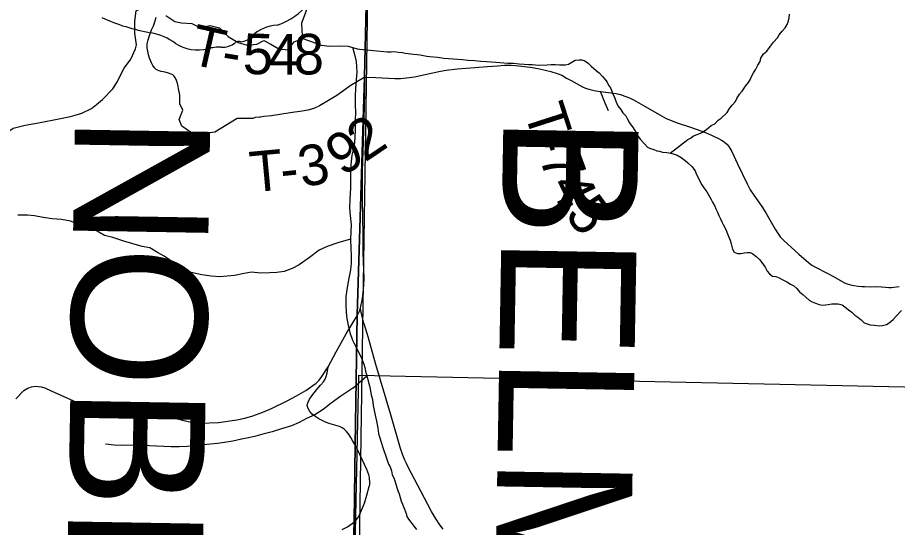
# Model space of a CAD drawing. Extents: x 0 to 34, y 0 to 22.
# Drawn here: x 26.601 to 27.832, y 19.383 to 20.097 of the extents above; entities that cross this region are included whole.
import ezdxf

# ---------------------------------------------------------------- set-up
doc = ezdxf.new("R2010")
doc.units = 0
for name, color, linetype in [('GM_X_Corporation', 7, 'Continuous'), ('GM_X_County', 7, 'Continuous'), ('GM_X_County_Text', 7, 'Continuous'), ('GM_X_Minor_River', 7, 'Continuous'), ('GM_X_State_Route', 7, 'Continuous'), ('GM_X_State_Shield', 7, 'Continuous'), ('GM_X_Township_Road', 7, 'Continuous'), ('GM_X_Township_Road_Text', 7, 'Continuous')]:
    doc.layers.add(name, color=color, linetype=linetype)

msp = doc.modelspace()

# ---------------------------------------------------------------- linework, layer by layer
at = {"layer": 'GM_X_Corporation'}
for points in [[(30.3167, 20.9), (27.1022, 20.9), (27.0898, 20.417), (27.0897, 20.4135), (27.089, 20.3692), (27.0873, 20.2665), (27.0907, 20.123), (27.0885, 20.1139), (27.0864, 20.0138), (27.0761, 19.6806), (27.0733, 19.498), (27.0719, 19.3912), (27.0487, 18.5805), (27.0419, 17.8236), (27.0349, 17.5522), (27.0234, 16.6611), (27.0124, 14.988), (27.0057, 14.5136), (27.2999, 14.5107), (27.8031, 14.5091), (28.4032, 14.497)], [(29.5503, 20.3788), (27.6751, 20.4106), (27.5829, 20.4116), (27.2336, 20.4152), (27.1239, 20.4163), (27.0898, 20.417), (27.0897, 20.4135), (27.089, 20.3692), (27.0873, 20.2665), (27.0907, 20.123), (27.0885, 20.1139), (27.0864, 20.0138), (27.0761, 19.6806), (27.0733, 19.498), (27.0719, 19.3912), (27.0487, 18.5805), (27.0419, 17.8236), (27.0349, 17.5522), (27.0234, 16.6611), (27.0124, 14.988), (27.0057, 14.5136), (27.2999, 14.5107), (27.8031, 14.5091), (28.4032, 14.497)], [(27.0234, 16.6611), (27.0349, 17.5522), (27.0419, 17.8236), (27.0487, 18.5805), (27.0719, 19.3912), (27.0733, 19.498), (27.0761, 19.6806), (27.0864, 20.0138), (27.0885, 20.1139), (27.0907, 20.123), (27.0873, 20.2665), (27.0031, 20.2673), (26.7822, 20.2704), (26.7196, 20.2707), (26.6351, 20.2734), (26.5702, 20.276), (26.2533, 20.2773), (25.4507, 20.2949), (24.5249, 20.3107), (24.0688, 20.3165), (24.0328, 20.3169), (23.5167, 20.3276), (23.5167, 14.5642)], [(27.0234, 16.6611), (27.0349, 17.5522), (27.0419, 17.8236), (27.0487, 18.5805), (27.0719, 19.3912), (27.0733, 19.498), (27.0761, 19.6806), (27.0864, 20.0138), (27.0885, 20.1139), (27.0907, 20.123), (27.0873, 20.2665), (27.0031, 20.2673), (26.7822, 20.2704), (26.7196, 20.2707), (26.6351, 20.2734), (26.5702, 20.276), (26.2533, 20.2773), (25.4507, 20.2949), (24.5249, 20.3107), (24.0688, 20.3165), (24.0328, 20.3169), (23.5167, 20.3276), (23.5167, 14.5642)]]:
    msp.add_lwpolyline(points, dxfattribs=at)
msp.add_lwpolyline([(27.9077, 19.5783), (27.8861, 18.5601), (27.0567, 18.5863), (27.0782, 19.5962)], close=True, dxfattribs=at)
at = {"layer": 'GM_X_County'}
msp.add_line((27.1022, 20.9), (27.0057, 14.5136), dxfattribs=at)
at = {"layer": 'GM_X_Minor_River'}
for points in [[(27.0002, 20.0673), (26.999, 20.0773), (26.9985, 20.0894), (27.0036, 20.1032), (27.0073, 20.1142), (27.0139, 20.1264), (27.0199, 20.1364), (27.0327, 20.1407), (27.0459, 20.1439), (27.0602, 20.1464), (27.0715, 20.1548), (27.0717, 20.1674), (27.0761, 20.1769), (27.0825, 20.1846)], [(26.8081, 20.0999), (26.8207, 20.0914), (26.8302, 20.0896), (26.8446, 20.0886), (26.8556, 20.0831), (26.87, 20.0856), (26.8832, 20.0823), (26.8955, 20.0703), (26.9096, 20.0618), (26.9221, 20.0581), (26.9353, 20.0598), (26.9455, 20.0649), (26.955, 20.0597), (26.9661, 20.053), (26.9793, 20.0516), (26.9879, 20.0628), (26.9999, 20.0675), (27.0132, 20.0627), (27.0258, 20.0583), (27.0379, 20.0566), (27.0515, 20.0571), (27.0636, 20.0569), (27.0761, 20.0532), (27.0798, 20.0525)], [(27.5144, 19.9071), (27.5388, 19.9259), (27.5426, 19.9279), (27.5471, 19.9314), (27.5535, 19.9338), (27.5587, 19.9361), (27.5651, 19.94), (27.5714, 19.9455), (27.5767, 19.9482), (27.5815, 19.9532), (27.5856, 19.9559), (27.5938, 19.9637), (27.5975, 19.9694), (27.6008, 19.974), (27.6056, 19.9794), (27.6075, 19.9836), (27.6115, 19.9898), (27.6149, 19.9936), (27.6196, 20.0009), (27.6237, 20.0059), (27.6267, 20.0105), (27.6281, 20.0144), (27.631, 20.0197), (27.6336, 20.0236), (27.6369, 20.0304), (27.6402, 20.0354), (27.6413, 20.04), (27.645, 20.0461), (27.6494, 20.05), (27.6546, 20.0569), (27.6587, 20.0623), (27.6646, 20.0685), (27.6668, 20.0727), (27.6709, 20.0777), (27.6753, 20.0827), (27.6779, 20.0873), (27.6797, 20.0923), (27.6808, 20.0965), (27.6814, 20.1014)], [(27.0693, 20.0552), (27.0717, 20.0471), (27.0748, 20.0354), (27.0754, 20.0206), (27.0744, 20.0103), (27.0738, 19.9974), (27.0732, 19.9868), (27.073, 19.9747), (27.0735, 19.9641), (27.0732, 19.9538), (27.073, 19.9394), (27.0728, 19.9288), (27.0718, 19.9174), (27.0686, 19.9044), (27.0672, 19.8908), (27.0666, 19.8813), (27.0667, 19.871), (27.0665, 19.8585), (27.0656, 19.8425), (27.0653, 19.8304), (27.0662, 19.8198), (27.0675, 19.8065), (27.0669, 19.7967), (27.0666, 19.7868), (27.0672, 19.7731), (27.0677, 19.7636), (27.0678, 19.753), (27.0668, 19.7435), (27.0643, 19.7317), (27.0626, 19.7215), (27.0601, 19.7063), (27.0603, 19.6926), (27.0612, 19.6782), (27.0633, 19.6657), (27.0657, 19.6559), (27.0696, 19.6453), (27.0714, 19.6415)], [(27.0798, 20.0525), (27.1182, 20.0487), (27.1238, 20.0488), (27.1276, 20.0492), (27.1341, 20.0486), (27.1394, 20.0479), (27.1432, 20.0472), (27.1473, 20.0465), (27.1549, 20.0455), (27.1598, 20.0452), (27.164, 20.0445), (27.1735, 20.0428), (27.1777, 20.0425), (27.1883, 20.0412), (27.1974, 20.0398), (27.2235, 20.038), (27.2315, 20.0374), (27.2402, 20.0368), (27.2493, 20.0358), (27.2569, 20.0352), (27.2702, 20.0343), (27.2868, 20.033), (27.2948, 20.0328), (27.3027, 20.0322), (27.3096, 20.0315), (27.3164, 20.0313), (27.3209, 20.031), (27.3255, 20.0307), (27.3293, 20.0304), (27.3421, 20.0306), (27.3478, 20.0311), (27.3538, 20.0312), (27.3595, 20.0309), (27.3641, 20.0306), (27.3679, 20.0307), (27.372, 20.0315), (27.3765, 20.0342), (27.3814, 20.037), (27.3866, 20.0378), (27.3904, 20.0375), (27.3946, 20.0361), (27.3992, 20.0331), (27.4035, 20.029), (27.4104, 20.0227), (27.4146, 20.0193), (27.4196, 20.0145), (27.4227, 20.0104), (27.4258, 20.0066), (27.4281, 20.0021), (27.4309, 19.9984), (27.4325, 19.9939), (27.434, 19.9901), (27.4368, 19.9841), (27.438, 19.9799), (27.4411, 19.9731), (27.445, 19.9679), (27.4481, 19.9634), (27.452, 19.9593), (27.4539, 19.9555), (27.4575, 19.9495), (27.4625, 19.9424), (27.466, 19.9364), (27.4687, 19.9315), (27.4722, 19.9266), (27.478, 19.9203), (27.4827, 19.9154), (27.4865, 19.9136), (27.4914, 19.9122), (27.4956, 19.9104), (27.4994, 19.9097), (27.5036, 19.9086), (27.5097, 19.9079), (27.5153, 19.9069), (27.5199, 19.9058), (27.5241, 19.904), (27.5298, 19.9007), (27.5352, 19.8966), (27.539, 19.8933), (27.5444, 19.8881), (27.5491, 19.8821), (27.5507, 19.8779), (27.5542, 19.8712), (27.5562, 19.867), (27.5585, 19.8625), (27.5612, 19.8584), (27.5655, 19.8528), (27.5694, 19.8464), (27.5714, 19.8422), (27.5737, 19.8385), (27.5768, 19.8329), (27.578, 19.8291), (27.5804, 19.8242), (27.5823, 19.8197), (27.5847, 19.8152), (27.5867, 19.811), (27.5882, 19.8073), (27.5922, 19.8001), (27.5945, 19.7941), (27.5965, 19.7892), (27.5981, 19.785), (27.5997, 19.7798)], [(27.0667, 19.7864), (27.0489, 19.7816), (27.0342, 19.7761), (27.023, 19.7711), (27.0091, 19.761), (26.9949, 19.7506), (26.9851, 19.7455), (26.9738, 19.7412), (26.9636, 19.74), (26.9538, 19.7394), (26.9409, 19.7389), (26.928, 19.7403), (26.9178, 19.7386), (26.9043, 19.7358), (26.8941, 19.7349), (26.8831, 19.734), (26.8718, 19.7346), (26.8585, 19.7367), (26.8437, 19.74), (26.8334, 19.7448), (26.8205, 19.7526), (26.806, 19.7626), (26.7964, 19.7678), (26.7858, 19.7745), (26.7748, 19.7763), (26.7603, 19.7807), (26.7493, 19.7836), (26.7338, 19.7887), (26.7224, 19.7919), (26.7121, 19.7979), (26.6999, 19.8027), (26.6897, 19.8063), (26.6748, 19.8118), (26.662, 19.814), (26.6491, 19.8149), (26.6362, 19.8167), (26.6244, 19.8192), (26.6146, 19.8202), (26.601, 19.82)], [(27.5997, 19.7798), (27.6017, 19.7726), (27.6037, 19.7684), (27.6083, 19.7666), (27.6132, 19.7667), (27.6177, 19.7672), (27.6219, 19.768), (27.626, 19.7677), (27.6298, 19.7659), (27.6345, 19.7622), (27.6391, 19.7581), (27.6425, 19.754), (27.6472, 19.7472), (27.65, 19.7416), (27.6534, 19.7378), (27.6576, 19.7345), (27.6622, 19.7342), (27.6668, 19.7324), (27.6721, 19.7298), (27.6775, 19.7269), (27.6828, 19.7235), (27.6874, 19.721), (27.6916, 19.7176), (27.6955, 19.7128), (27.7001, 19.709), (27.7089, 19.7012), (27.7128, 19.699), (27.7177, 19.6968), (27.7227, 19.695), (27.7268, 19.6943), (27.7318, 19.6944), (27.7355, 19.6952), (27.7404, 19.6961), (27.7446, 19.6962), (27.7495, 19.6959), (27.7548, 19.6945), (27.7587, 19.6919), (27.7637, 19.6878), (27.7687, 19.6841), (27.7729, 19.68), (27.7771, 19.6774), (27.7817, 19.6737), (27.7859, 19.6696), (27.7901, 19.6678), (27.7943, 19.6667), (27.7996, 19.666), (27.8076, 19.6654), (27.8114, 19.6655), (27.817, 19.6671), (27.8208, 19.6694), (27.8264, 19.6741), (27.8308, 19.6787), (27.8379, 19.6868)], [(27.0714, 19.6415), (27.0818, 19.6215), (27.0834, 19.6162), (27.0854, 19.6113), (27.0866, 19.6068), (27.0878, 19.6019), (27.0911, 19.5898), (27.0919, 19.5857), (27.0935, 19.5796), (27.0948, 19.5739), (27.0956, 19.5686), (27.0973, 19.5618), (27.0985, 19.5535), (27.0994, 19.549), (27.101, 19.5403), (27.1023, 19.5357), (27.1031, 19.5316), (27.1039, 19.527), (27.1048, 19.5217), (27.106, 19.5145), (27.1073, 19.5096), (27.1101, 19.501), (27.1113, 19.4964), (27.1137, 19.4893), (27.1153, 19.4855), (27.1177, 19.4783), (27.1201, 19.4715), (27.122, 19.4678), (27.124, 19.4621), (27.1252, 19.4564), (27.1272, 19.4523), (27.1292, 19.4466), (27.1316, 19.4387), (27.1336, 19.4334), (27.1348, 19.4297), (27.136, 19.4247), (27.1376, 19.4198), (27.1396, 19.4153), (27.1412, 19.4108), (27.1444, 19.4025), (27.1456, 19.3983), (27.1479, 19.3946), (27.151, 19.3901), (27.1553, 19.3845), (27.1591, 19.38)], [(27.0701, 19.5777), (27.0897, 19.5951)], [(27.0701, 19.5777), (27.0532, 19.5665), (27.0397, 19.5569), (27.0284, 19.548), (27.0168, 19.5406), (27.0052, 19.5352), (26.9946, 19.5297), (26.9841, 19.525), (26.9702, 19.5211), (26.957, 19.5167), (26.9438, 19.5135), (26.934, 19.5107), (26.9238, 19.5083), (26.914, 19.5063), (26.9019, 19.5039), (26.8902, 19.5018), (26.8804, 19.5006), (26.8706, 19.4997), (26.8604, 19.4984), (26.8494, 19.4972), (26.8377, 19.4962), (26.8268, 19.4957), (26.8154, 19.4956), (26.8052, 19.4962), (26.795, 19.4965), (26.7851, 19.4971), (26.7723, 19.4981), (26.7466, 19.4978), (26.736, 19.498), (26.7238, 19.4997)]]:
    msp.add_lwpolyline(points, dxfattribs=at)
at = {"layer": 'GM_X_State_Route'}
for points in [[(27.0763, 19.6801), (27.0791, 19.6859), (27.0806, 19.6898), (27.0818, 19.695), (27.0829, 19.7006), (27.0839, 19.7073), (27.0847, 19.7164), (27.0851, 19.7224), (27.0857, 19.7312), (27.0854, 19.7437), (27.0849, 19.7555), (27.0844, 19.7673), (27.0842, 19.7936), (27.0841, 19.8164), (27.0835, 19.8419), (27.0833, 19.8545), (27.0835, 19.8819), (27.085, 19.9229), (27.0857, 19.9547), (27.0865, 19.9923), (27.0866, 20.0133), (27.0869, 20.0302), (27.0871, 20.0439), (27.0876, 20.0697), (27.0881, 20.0883), (27.0886, 20.0987)], [(27.1966, 19.3803), (27.1919, 19.3866), (27.1856, 19.3959), (27.1802, 19.4053), (27.1651, 19.4336), (27.1479, 19.4665), (27.1449, 19.4726), (27.1429, 19.4772), (27.14, 19.4841), (27.1367, 19.4932), (27.1346, 19.5001), (27.1231, 19.5406), (27.1023, 19.6109), (27.0914, 19.6497), (27.0856, 19.668), (27.0855, 19.6683), (27.0829, 19.6787), (27.0816, 19.6838), (27.0806, 19.6898)], [(26.598, 19.5628), (26.6091, 19.5745), (26.6148, 19.5781), (26.6201, 19.5797), (26.6252, 19.5805), (26.6338, 19.5796), (26.6387, 19.5782), (26.6477, 19.5743), (26.6612, 19.568), (26.6832, 19.5582), (26.6937, 19.5541), (26.7043, 19.5504), (26.716, 19.5479), (26.7348, 19.5457), (26.7671, 19.5426), (26.7961, 19.5397), (26.8097, 19.538), (26.8227, 19.5352), (26.8354, 19.5323), (26.8459, 19.53), (26.8564, 19.5288), (26.8818, 19.5297), (26.9075, 19.5335), (26.9189, 19.536), (26.9301, 19.5393), (26.9439, 19.5442), (26.956, 19.5492), (26.9779, 19.56), (26.9912, 19.5671), (27.004, 19.5746), (27.0138, 19.5815), (27.0184, 19.585), (27.0226, 19.5893), (27.0266, 19.5941), (27.0354, 19.6078), (27.0467, 19.6288), (27.0608, 19.6538), (27.0763, 19.6801)]]:
    msp.add_lwpolyline(points, dxfattribs=at)
at = {"layer": 'GM_X_State_Shield'}
for centre, major_axis, start_param, end_param in [((26.9307, 20.1509), (0.0874, 0), 5.101752, 6.440018), ((26.8432, 20.2724), (0.2524, 0), 4.195997, 4.488961), ((26.9676, 20.048), (0.0479, 0), 1.647645, 2.488434), ((26.7679, 20.0143), (0.079, 0), 0.823519, 1.323587), ((26.9069, 20.0848), (0.0282, 0), 4.937069, 5.64225), ((26.8534, 20.0916), (0.0501, 0), 4.026481, 4.996735), ((26.8823, 20.0224), (0.0412, 0), 1.495662, 1.94098), ((26.886, 20.0766), (0.0267, 0), 4.691044, 5.507374), ((26.9101, 20.0573), (0.00752, 0), 1.147584, 2.315152)]:
    msp.add_ellipse(centre, major_axis=major_axis, ratio=0.8, start_param=start_param, end_param=end_param, dxfattribs=at)
at = {"layer": 'GM_X_Township_Road'}
for points in [[(26.711, 19.9751), (26.7193, 19.982), (26.7339, 19.9973), (26.7406, 20.0074), (26.7469, 20.021), (26.7498, 20.0259), (26.759, 20.0388), (26.7657, 20.0532), (26.7671, 20.0587), (26.7645, 20.0749), (26.7648, 20.0919), (26.7664, 20.1061), (26.7766, 20.1112), (26.7846, 20.1241)], [(26.8245, 20.0039), (26.8238, 20.0063), (26.8232, 20.0086), (26.8216, 20.0119), (26.8196, 20.0146), (26.8177, 20.0165), (26.8157, 20.0175), (26.8118, 20.0191), (26.8074, 20.0203), (26.8016, 20.0212), (26.7975, 20.0227), (26.7947, 20.0243), (26.7922, 20.0266), (26.7901, 20.0298), (26.7882, 20.0334), (26.7853, 20.04), (26.7839, 20.0447), (26.7827, 20.0497), (26.7821, 20.054), (26.7822, 20.0599), (26.7835, 20.0658), (26.7853, 20.0717), (26.7882, 20.0799), (26.7907, 20.0855), (26.7933, 20.0923), (26.7944, 20.0976)], [(27.0866, 20.0133), (27.1021, 20.013), (27.1289, 20.0115), (27.1365, 20.0116), (27.145, 20.0123), (27.1563, 20.014), (27.1712, 20.0173), (27.1929, 20.0218), (27.2008, 20.0233), (27.2162, 20.025), (27.2284, 20.026), (27.2587, 20.0283), (27.2724, 20.0294), (27.2824, 20.0302), (27.2918, 20.0303), (27.2979, 20.0299), (27.3063, 20.029), (27.3184, 20.0274), (27.3236, 20.0266), (27.3315, 20.0252), (27.3394, 20.0234), (27.3472, 20.0213), (27.3559, 20.0187), (27.3624, 20.016), (27.3693, 20.0122), (27.3755, 20.0088), (27.3914, 19.9998), (27.3958, 19.998), (27.4003, 19.9965), (27.4061, 19.995), (27.4102, 19.9942), (27.4169, 19.9933), (27.4281, 19.9919), (27.4388, 19.9903), (27.4449, 19.989), (27.4508, 19.987), (27.4573, 19.9843), (27.464, 19.981), (27.4769, 19.9737), (27.5022, 19.9591), (27.5084, 19.9557), (27.5123, 19.9539), (27.5181, 19.9516), (27.5255, 19.9488), (27.5413, 19.9437), (27.5585, 19.938), (27.5668, 19.9345), (27.5741, 19.9313), (27.582, 19.9276), (27.5863, 19.9252), (27.5899, 19.9227), (27.5935, 19.9196), (27.5962, 19.9165), (27.5979, 19.9139), (27.6005, 19.9095), (27.6086, 19.8922), (27.622, 19.8639), (27.6237, 19.8604), (27.6263, 19.8556), (27.6315, 19.8481), (27.6426, 19.8322), (27.6481, 19.8232), (27.6557, 19.8105), (27.6614, 19.8005), (27.6646, 19.7953), (27.6683, 19.79), (27.6734, 19.7845), (27.6945, 19.7655), (27.7014, 19.7593), (27.708, 19.7537), (27.7127, 19.7502), (27.7176, 19.7472), (27.7342, 19.7387), (27.7427, 19.7342), (27.7548, 19.7271), (27.7585, 19.7253), (27.7618, 19.724), (27.7666, 19.7227), (27.7715, 19.7215), (27.7775, 19.7206), (27.7825, 19.7202), (27.7866, 19.7201), (27.7947, 19.7199), (27.8034, 19.7202), (27.8101, 19.72), (27.8156, 19.7194), (27.8204, 19.7189), (27.824, 19.7188), (27.8273, 19.7191), (27.8349, 19.7201)], [(26.9453, 19.9581), (26.9407, 19.9575), (26.9393, 19.9573), (26.9334, 19.9567), (26.9297, 19.9556), (26.9197, 19.9555), (26.908, 19.9556), (26.8768, 19.9364), (26.8575, 19.9338), (26.8427, 19.9363), (26.8305, 19.9448), (26.8269, 19.9542), (26.8319, 19.9672), (26.8277, 19.976), (26.8279, 19.9819), (26.8277, 19.9881), (26.8259, 19.9975), (26.8247, 20.0032), (26.8245, 20.0039)], [(27.0866, 20.0133), (27.0663, 20.0014), (27.0572, 19.9947), (27.0473, 19.9878), (27.036, 19.9807), (27.0233, 19.9733), (27.0152, 19.9697), (27.0067, 19.9672), (26.9988, 19.9657), (26.9824, 19.9636), (26.956, 19.9594), (26.9453, 19.9581)], [(27.4279, 19.9662), (27.423, 19.9772), (27.4169, 19.9933)], [(26.5499, 19.9122), (26.5945, 19.9421), (26.6112, 19.9463), (26.6297, 19.9496), (26.6581, 19.9549), (26.6747, 19.9585), (26.6814, 19.96), (26.6906, 19.9628), (26.7039, 19.9693), (26.711, 19.9751)], [(27.0735, 19.4974), (27.0694, 19.5045), (27.0671, 19.5087), (27.0639, 19.5139), (27.061, 19.5174), (27.0579, 19.5203), (27.0549, 19.5224), (27.0514, 19.524), (27.0383, 19.5281), (27.0318, 19.5305), (27.0252, 19.5334), (27.0211, 19.5357), (27.0167, 19.5385), (27.0131, 19.5415), (27.0096, 19.5452), (27.0072, 19.5493), (27.0061, 19.5535), (27.0065, 19.5558), (27.0072, 19.5585), (27.0091, 19.5623), (27.0124, 19.567), (27.019, 19.5756), (27.0247, 19.5821), (27.0287, 19.5866), (27.0312, 19.5904), (27.0327, 19.5942), (27.0339, 19.599), (27.0354, 19.6078)], [(27.0721, 19.3906), (27.0736, 19.3922), (27.0768, 19.3962), (27.0781, 19.3983), (27.0793, 19.4003), (27.0835, 19.4105), (27.0861, 19.417), (27.0896, 19.4281), (27.093, 19.44), (27.0937, 19.443), (27.0939, 19.4448), (27.0933, 19.4526), (27.0921, 19.4567), (27.0893, 19.4641), (27.0863, 19.4712), (27.0836, 19.477), (27.0795, 19.4851), (27.0735, 19.4974)], [(27.055, 19.3798), (27.0624, 19.3839), (27.0721, 19.3906)]]:
    msp.add_lwpolyline(points, dxfattribs=at)

# ---------------------------------------------------------------- texts
at = {"layer": 'GM_X_County_Text'}
for s, rotation, p in [('NOBLE COUNTY', 269.0214, (26.6811, 19.9608)), ('BELMONT COUNTY', 268.998, (27.2809, 19.9608))]:
    msp.add_text(s, height=0.189394, rotation=rotation, dxfattribs=at).set_placement(p)
at = {"layer": 'GM_X_Township_Road_Text'}
for s, rotation, p in [('T', 347.1384, (26.8387, 20.0328)), ('5', 358.6139, (26.9155, 20.018)), ('4', 0.006, (26.952, 20.0171)), ('8', 0.3588, (26.9874, 20.0171)), ('-', 350.6353, (26.8839, 20.0226)), ('T', 287.8807, (27.309, 19.9661)), ('2', 34.0159, (27.0867, 19.8934)), ('9', 31.9773, (27.0552, 19.8737)), ('-', 288.3175, (27.3222, 19.9252)), ('3', 10.2183, (26.9989, 19.859)), ('T', 5.3473, (26.9281, 19.852)), ('7', 290.0325, (27.3301, 19.9013)), ('-', 5.7996, (26.9709, 19.856)), ('4', 295.6491, (27.3445, 19.8628)), ('5', 306.773, (27.3658, 19.821))]:
    msp.add_text(s, height=0.0568, rotation=rotation, dxfattribs=at).set_placement(p)

doc.saveas('drawing.dxf')
